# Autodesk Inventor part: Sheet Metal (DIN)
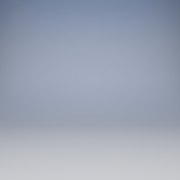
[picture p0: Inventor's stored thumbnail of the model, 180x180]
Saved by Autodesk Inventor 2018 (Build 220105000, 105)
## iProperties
Created: 2017-02
Part Number: Sheet Metal (DIN)
Material: Ogólny
Document SubType Name: Konstrukcja blachowa
Density: 1 g/cm^3
Appearance: Domyślna
Sheet Metal Rule: Domyślny_mm
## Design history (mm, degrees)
other parameters: "Grubość" = 0.5 (derived), "WspółczynnikK" = 4.4, "PromieńGięcia" = 0.5 (= Grubość), "SzerokośćGięciaPodcięcia" = 0.5 (= Grubość), "GłębokośćGięciaPodcięcia" = 0.25 (= 0.5 x Grubość), "RozmiarPodcięciaNarożnika" = 2 (= 4 x Grubość), "OdstępPołączenia" = 0.01, "MinimalnaPozostałość" = 1 (= 2 x Grubość), "PromieńPrzejścia" = 0.5 (= PromieńGięcia), "Rozmiar_promienia_Jacobiego" = 0.5 (= PromieńGięcia), "Wielk_odstępu" = 0.5 (= Grubość)
